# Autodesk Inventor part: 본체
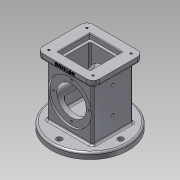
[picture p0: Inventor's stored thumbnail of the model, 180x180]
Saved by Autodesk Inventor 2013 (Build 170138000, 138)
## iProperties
Created: 2018-10
Part Number: 본체
Material: 알루미늄 6061
Document SubType Name: Modeling
Designer: hana-max10
Density: 2.40731 g/cm^3
Mass: 879.367 g
Surface Area: 748.201 cm^2
Volume: 365.29 cm^3
Author: hana-max10
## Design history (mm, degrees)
sketch "스케치1"
  geometry: C1 r 62.5 at (0, 0); 1 further point
  constraints: 1 centre point, 1 coincident
  dimensions: "d0" = 125 diameter of C1
extrude "돌출1" new body sketch "스케치1" distance "d2" = 10; taper "d3" = 0 deg
sketch "스케치2"
  geometry: L1 (-37, 33)-(37, 33); L2 (37, 33)-(37, -33); L3 (37, -33)-(-37, -33); L4 (-37, -33)-(-37, 33); L5 (-37, 33)-(37, -33); L6 (37, 33)-(-37, -33); C1 r 62.5 at (0, 0) reference
  constraints: 12 end point, 2 midpoint, 2 parallel, 1 horizontal, 1 perpendicular
  dimensions: "d4" = 74 distance of L2.end L3.end; "d7" = 66 distance of L1.end L2.end
extrude "돌출2" join sketch "스케치2" distance "d8" = 88; taper "d9" = 0 deg
sketch "스케치3"
  geometry: L1 (-46, 41)-(46, 41); L2 (46, 41)-(46, -41); L3 (46, -41)-(-46, -41); L4 (-46, -41)-(-46, 41); L5 (-46, 41)-(46, -41); L6 (46, 41)-(-46, -41); 1 further point
  constraints: 12 end point, 2 midpoint, 2 parallel, 1 horizontal, 1 perpendicular
  dimensions: "d10" = 92 distance of L1.start L1.end; "d12" = 82 distance of L1.end L2.end
extrude "돌출3" join sketch "스케치3" distance "d13" = 10; taper "d14" = 0 deg
sketch "스케치4"
  geometry: L1 (-26, 26)-(26, 26); L2 (26, 26)-(26, -26); L3 (26, -26)-(-26, -26); L4 (-26, -26)-(-26, 26); L5 (-26, 26)-(26, -26); L6 (26, 26)-(-26, -26); 1 further point
  constraints: 12 end point, 2 midpoint, 2 parallel, 1 horizontal, 1 perpendicular
  dimensions: "d15" = 52 distance of L1.start L1.end; "d17" = 52 distance of L1.end L2.end
extrude "돌출4" cut sketch "스케치4" distance "d18" = 8; taper "d19" = 0 deg
sketch "스케치6"
  geometry: L1 (-22, -22)-(22, -22); L2 (22, -22)-(22, 22); L3 (22, 22)-(-22, 22); L4 (-22, 22)-(-22, -22); L5 (-22, -22)-(22, 22); L6 (22, -22)-(-22, 22); 1 further point
  constraints: 12 end point, 2 midpoint, 2 parallel, 1 horizontal, 1 perpendicular
  dimensions: "d25" = 44 distance of L2.end L3.end; "d27" = 44 distance of L1.end L2.end
extrude "돌출5" cut sketch "스케치6" distance "d28" = 74; taper "d29" = 0 deg
fillet "모깎기1" dims "d37" = 3
node "작업 평면3"
sketch "스케치8"
  geometry: L1 (-88, 63)-(0, 63) reference; L2 (0, -3)-(-88, -3) reference; L3 (-98, 4)-(-98, 56) reference; L4 (-98, 4)-(-90, 4) reference; L5 (-90, 4)-(-90, 56) reference; L6 (-98, 56)-(-90, 56) reference; L7 (-90, 52)-(-16, 52) reference; L8 (-90, 8)-(-90, 52) reference; L9 (-90, 8)-(-16, 8) reference; L10 (10, -32.5)-(10, 92.5) reference; L11 (0, 92.5)-(0, -32.5) reference; L12 (10, -32.5)-(10, 92.5) reference; L13 (-88, -11)-(-88, 71) reference; L14 (-88, -11)-(-98, -11) reference; L15 (-98, 71)-(-98, -11) reference; L16 (-88, 71)-(-98, 71) reference; L17 (-44, -3)-(-44, 63); L18 (-44, -3)-(-79, -3); L19 (-79, 0)-(-79, -3); L20 (-79, 0)-(-68, 0); L21 (-68, 0)-(-68, 60); L22 (-68, 60)-(-79, 60); L23 (-79, 60)-(-79, 63); L24 (-79, 63)-(-44, 63); L25 (-16, 8)-(-16, 52) reference; 3 further points
  constraints: 16 end point, 3 horizontal, 3 vertical, 2 midpoint, 2 point on line
  dimensions: "d38" = 3 distance between parallel lines of L24 L22; "d40" = 3 distance between parallel lines of L2 L20; "d41" = 70 diameter of L19 L17; "d42" = 70 diameter of L23 L17; "d43" = 48 diameter of L21 L17
revolve "회전1" sketch "스케치8" stored, may be unused: angle "d44" = 90 deg
node "작업 평면4"
sketch "스케치12"
  geometry: L1 (10, 2)-(-5.521, 4.737); L2 (-8, 7.691)-(-8, 30); L3 (-8, 30)-(10, 30); L4 (10, 30)-(10, 2); A1 r 3 centre (-5, 7.691) between (-8, 7.691) and (-5.521, 4.737)
  constraints: 8 end point, 2 point on circle, 2 tangent, 2 vertical, 1 centre point, 1 horizontal
  dimensions: "d48" = 18 distance between parallel lines of L2 L4; "d50" = 80 deg angle of L4 L1; "d52" = 56 diameter of L1.start L3; "d53" = 3 radius of A1
revolve "회전2" sketch "스케치12" stored, may be unused: angle "d54" = 90 deg
sketch "스케치13"
  geometry: C1 r 24 at (0, 0) reference; 2 further points
  constraints: 1 vertical alignment
  dimensions: "d55" = 29 distance of C1.centre point (0, -29)
hole "구멍1" sketch "스케치13" at (0, -29) diameter "d56" = 3.242; stored, may be unused: countersink angle "d60" = 90 deg, drill point angle "d62" = 118 deg; dims "d57" = 4, "d58" = 4, "d59" = 2, "d61" = 6
sketch "스케치14"
  geometry: L1 (10, -32.5)-(10, 92.5) reference; 4 further points
  constraints: 2 horizontal alignment, 1 midpoint
  dimensions: "d66" = 37 distance from line of L1 point (-27, 30); "d67" = 43 distance of point (-70, 30) point (-27, 30)
hole "구멍2" sketch "스케치14" at (-27, 30), (-70, 30) diameter "d68" = 4.134; stored, may be unused: countersink angle "d72" = 90 deg, drill point angle "d74" = 0 deg; dims "d69" = 6, "d70" = 4, "d71" = 2, "d73" = 15
sketch "스케치15" dims "d75" = 100
  geometry: C1 r 62.5 at (0, 0) reference; C2 r 4.5 at (0, 50); 2 further points
  constraints: 2 coincident, 2 vertical alignment, 1 centre point, 2 other
  dimensions: "d77" = 9 diameter of C2
extrude "돌출6" cut sketch "스케치15" distance "d78" = 12; taper "d79" = 0 deg
fillet "모깎기2" dims "d83" = 10
sketch "스케치17"
  geometry: A1 r 10 centre (-36, 31) between (-36, 41) and (-46, 31) reference; A2 r 10 centre (-36, -31) between (-46, -31) and (-36, -41) reference; A3 r 10 centre (36, -31) between (36, -41) and (46, -31) reference; A4 r 10 centre (36, 31) between (46, 31) and (36, 41) reference; 5 further points
  constraints: 4 coincident
hole "구멍3" sketch "스케치17" at (-36, 31), (-36, -31), (36, -31), (36, 31) diameter "d84" = 3.242; stored, may be unused: countersink angle "d88" = 90 deg, drill point angle "d90" = 118 deg; dims "d85" = 4, "d86" = 4, "d87" = 2, "d89" = 6
fillet "모깎기3" dims "d91" = 3
fillet "모깎기4" dims "d92" = 3
fillet "모깎기5" dims "d93" = 3
chamfer "모따기1" distance "d94" = 1; stored, may be unused: second distance "d95" = 2, angle "d96" = 45 deg
fillet "모깎기6" dims "d97" = 3
sketch "스케치20"
  geometry: L1 (0, 10)-(72, 10) reference; L2 (-10, 10)-(-10, 0) reference; L3 (0, 10)-(-10, 10) reference; L4 (-10, 10)-(-10, 0) reference; L5 (-10, 0)-(0, 0) reference; L6 (0, 0)-(0, 10) reference; L7 (82, 10)-(72, 10) reference; L8 (72, 10)-(72, 0) reference; L9 (72, 0)-(82, 0) reference; L10 (82, 0)-(82, 10) reference; 2 further points
  constraints: 1 other
  dimensions: "d98" = 46 distance from line of point (36, 6) L2; "d99" = 4 distance from line of L1 point (36, 6)
feature "엠보싱1" sketch "스케치20" dims "d3" = 0, "d100" = 0.5, "d101" = 0
fillet "모깎기7" dims "d102" = 3
node "솔리드1"
pattern_circular "원형 패턴1" dims angle "d64" = 360 deg
mirror "대칭1"
pattern_circular "원형 패턴2" dims angle "d81" = 360 deg
node "투영된 루프7"
node "투영된 루프8"
node "투영된 루프9"
node "투영된 루프10"
node "투영된 루프12"
node "투영된 루프13"
